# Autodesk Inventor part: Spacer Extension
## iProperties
Shininess: 64.0
Length Units: 11272
Angle Units: 11279
Time Units: 11290
Mass Units: 11286
Length Display Precision: 3
Angle Display Precision: 2
Compacted: True
Part Number: Spacer Extension
Document SubType Name: Modeling
Created: 2003-08
Designer: FT User
Manufacturer: Standard
Standards Organization: Custom
Density: 0.0
Volumn: 0.0
Area: 0.0
PropertySet Name: Model Information
Control State: 0
Master: False
Checked Out: False
Author: FT User
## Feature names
1. Extrusion2
2. Extrusion3
3. Extrusion4
